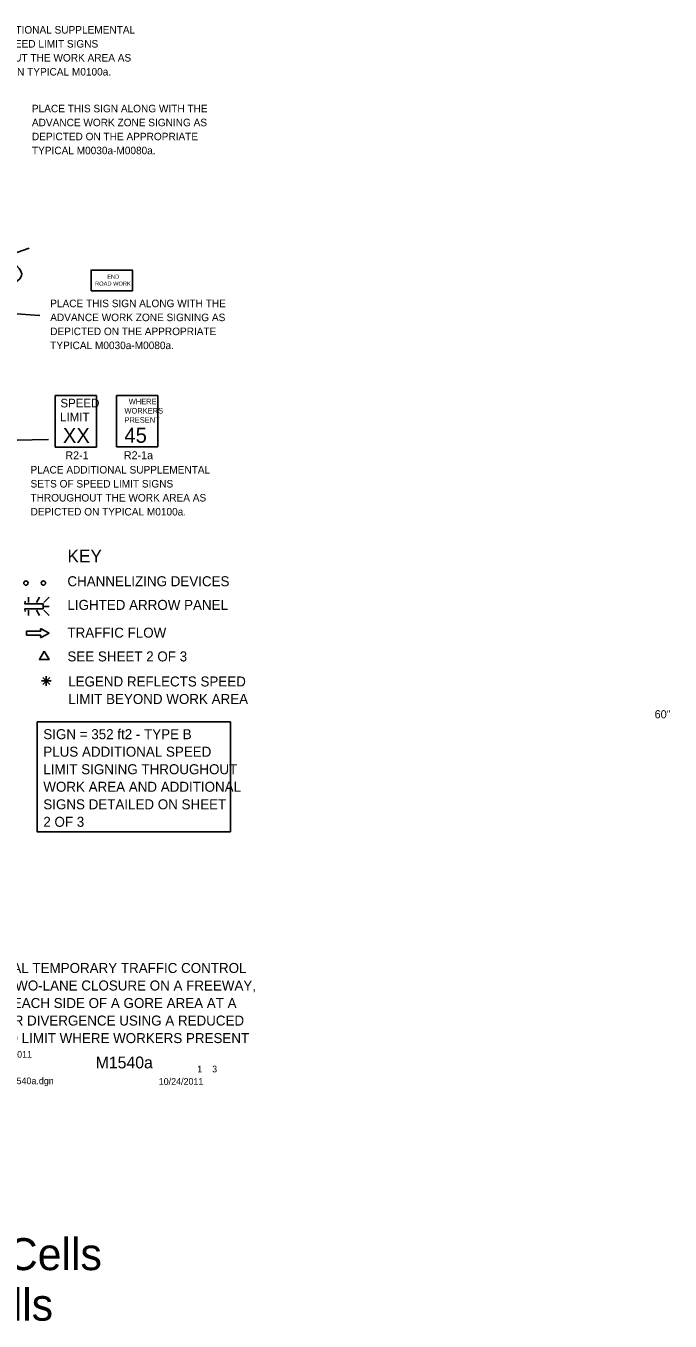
# Model space of a CAD drawing. Extents: x 16452 to 19504, y 5713 to 7079.
# Drawn here: x 17224 to 17823, y 5713 to 6918 of the extents above; entities that cross this region are included whole.
import ezdxf

# ---------------------------------------------------------------- set-up
doc = ezdxf.new("R2010")
doc.units = 0
for name, color, linetype in [('BORDER', 7, 'Continuous'), ('BORDER_SIGNAL_WO', 7, 'Continuous'), ('MT_SCRATCH_LEVEL_E', 7, 'Continuous'), ('PAVT_EDGE_EX', 7, 'Continuous'), ('TRAFFIC_SIGNS_PR', 7, 'Continuous'), ('TYPICAL_TEXT_DIMEN_EX', 7, 'Continuous'), ('TYPICAL_TEXT_DIMEN_PR', 7, 'Continuous')]:
    doc.layers.add(name, color=color, linetype=linetype)

msp = doc.modelspace()

# ---------------------------------------------------------------- linework, layer by layer
at = {"layer": 'MT_SCRATCH_LEVEL_E'}
for p, q in [((17238.3, 6354.9), (17225.1, 6354.9)), ((17225.1, 6354.9), (17225.1, 6351.2)), ((17225.1, 6351.2), (17238.3, 6351.2)), ((17238, 6356.7), (17238.3, 6354.9)), ((17238.3, 6351.2), (17238, 6349.4)), ((17245.9, 6353.1), (17238.7, 6357.2)), ((17238.7, 6348.9), (17245.9, 6353.1))]:
    msp.add_line(p, q, dxfattribs=at)
for centre, start, end in [((17238.5, 6356.8), 60.4248, 189.9638), ((17238.5, 6349.4), 170.0362, 299.7731)]:
    msp.add_arc(centre, 0.463, start, end, dxfattribs=at)
at = {"layer": 'PAVT_EDGE_EX'}
msp.add_arc((17319.9, 6425.6), 300, 107.923, 180, dxfattribs=at)
at = {"layer": 'TRAFFIC_SIGNS_PR'}
for p, q in [((17251.5, 6574.1), (17289.9, 6574.1)), ((17251.5, 6526.1), (17251.5, 6574.1)), ((17289.9, 6526.1), (17289.9, 6574.1)), ((17308.7, 6574.2), (17347.1, 6574.2)), ((17308.7, 6526.2), (17308.7, 6574.2)), ((17347.1, 6526.2), (17347.1, 6574.2)), ((17251.5, 6526.1), (17289.9, 6526.1)), ((17308.7, 6526.2), (17347.1, 6526.2)), ((17226.9, 6381.5), (17226.9, 6386.5)), ((17234.1, 6381.5), (17236.9, 6386.5)), ((17241, 6381.5), (17245.9, 6386.5)), ((17226.9, 6374.4), (17226.9, 6369.5)), ((17237, 6369.5), (17234.1, 6374.4)), ((17241, 6378), (17245.9, 6378)), ((17241, 6374.4), (17245.9, 6369.5))]:
    msp.add_line(p, q, dxfattribs=at)
msp.add_lwpolyline([(17285, 6671.5), (17323.4, 6671.5), (17323.4, 6690.7), (17285, 6690.7)], close=True, dxfattribs=at)
msp.add_lwpolyline([(17223.7, 6373.3), (17223.3, 6375.6), (17240.3, 6375.6), (17240.3, 6380.4), (17223.3, 6380.4), (17223.7, 6382.7)], dxfattribs=at)
for centre in [(17224.4, 6399.7), (17240.7, 6399.7)]:
    msp.add_circle(centre, 2, dxfattribs=at)
at = {"layer": 'TYPICAL_TEXT_DIMEN_EX'}
msp.add_lwpolyline([(17234.8, 6270.5), (17414.5, 6270.5), (17414.5, 6168.4), (17234.8, 6168.4)], close=True, dxfattribs=at)
at = {"layer": 'TYPICAL_TEXT_DIMEN_PR'}
for p, q in [((17240.1, 6311.7), (17246.5, 6305.4)), ((17246.5, 6311.7), (17240.1, 6305.4)), ((17243.3, 6308.6), (17243.3, 6313)), ((17243.3, 6308.6), (17238.8, 6308.6)), ((17243.3, 6308.6), (17246.5, 6308.6)), ((17243.3, 6308.6), (17247.8, 6308.6)), ((17243.3, 6308.6), (17243.3, 6304.1))]:
    msp.add_line(p, q, dxfattribs=at)
msp.add_lwpolyline([(17241.4, 6336.3), (17236.9, 6328.5), (17246, 6328.5)], close=True, dxfattribs=at)
for points in [[(17211.5, 6698.9), (17216.4, 6694.3), (17226.4, 6684.9), (17205.5, 6674.4), (17175.7, 6652.8), (17212.4, 6650.2), (17237.4, 6648.4)], [(17102.5, 6551), (17180.2, 6550.2), (17180.7, 6541.4), (17158.2, 6539.5), (17158, 6531.4), (17245.5, 6533)]]:
    msp.add_open_spline(points, degree=3, dxfattribs=at)

# ---------------------------------------------------------------- texts
at = {"layer": 'BORDER'}
for s, p in [('TYPICAL TEMPORARY TRAFFIC CONTROL', (17175.2, 6037.1)), ('FOR A TWO-LANE CLOSURE ON A FREEWAY,', (17165.4, 6020.8)), ('ONE ON EACH SIDE OF A GORE AREA AT A ', (17159.7, 6004.5)), ('MAJOR DIVERGENCE USING A REDUCED', (17178.5, 5988.2)), ('SPEED LIMIT WHERE WORKERS PRESENT', (17174.9, 5971.9))]:
    msp.add_text(s, height=9.3, dxfattribs=at).set_placement(p)
at = {"layer": 'BORDER_SIGNAL_WO'}
for s, height, p in [('    OCTOBER 2011    ', 6.2, (17159.1, 5958.3)), ('    M1540a   ', 11, (17272.9, 5948.4)), (' 1    3 ', 6.2, (17381.4, 5944.7)), ('PW RD/TS/Typicals/Signs/MT FWY/M1540a.dgn      ', 6.2, (17070.6, 5933.7)), ('10/24/2011    ', 6.2, (17347.9, 5933.1)), ('AS = 0.8 for Sign Cells', 29.727, (16894, 5760.8)), ('     1.0 for Text Cells', 29.727, (16894, 5713.8))]:
    msp.add_text(s, height=height, dxfattribs=at).set_placement(p)
at = {"layer": 'TRAFFIC_SIGNS_PR'}
for s, height, p in [('PLACE ADDITIONAL SUPPLEMENTAL', 7, (17159, 6910.6)), ('SETS OF SPEED LIMIT SIGNS', 7, (17159, 6897.6)), ('THROUGHOUT THE WORK AREA AS', 7, (17159, 6884.6)), ('DEPICTED ON TYPICAL M0100a.', 7, (17159, 6871.6)), ('PLACE THIS SIGN ALONG WITH THE', 7, (17230, 6837.4)), ('ADVANCE WORK ZONE SIGNING AS', 7, (17230, 6824.4)), ('DEPICTED ON THE APPROPRIATE', 7, (17230, 6811.4)), ('TYPICAL M0030a-M0080a.', 7, (17230, 6798.4)), ('END', 3.83, (17300, 6682.6)), ('ROAD WORK', 3.83, (17288.7, 6676.2)), ('PLACE THIS SIGN ALONG WITH THE', 7, (17247, 6656.2)), ('ADVANCE WORK ZONE SIGNING AS', 7, (17247, 6643.2)), ('DEPICTED ON THE APPROPRIATE', 7, (17247, 6630.2)), ('TYPICAL M0030a-M0080a.', 7, (17247, 6617.2)), ('SPEED', 8, (17256.5, 6563)), ('WHERE', 5.2, (17320, 6565.9)), ('LIMIT', 8, (17256.2, 6550.2)), ('WORKERS', 5.2, (17316, 6557.3)), ('PRESENT', 5.2, (17316, 6548.7)), ('XX', 14.03, (17258.8, 6529.9)), ('45', 14.03, (17316, 6530.1)), ('R2-1', 7.44, (17261.1, 6514.7)), ('R2-1a', 7.44, (17315.5, 6514.8)), ('PLACE ADDITIONAL SUPPLEMENTAL', 7, (17228.7, 6501.5)), ('SETS OF SPEED LIMIT SIGNS', 7, (17228.7, 6488.5)), ('THROUGHOUT THE WORK AREA AS', 7, (17228.7, 6475.5)), ('DEPICTED ON TYPICAL M0100a.', 7, (17228.7, 6462.5))]:
    msp.add_text(s, height=height, dxfattribs=at).set_placement(p)
at = {"layer": 'TYPICAL_TEXT_DIMEN_EX'}
for s, height, p in [('KEY', 12, (17263, 6418.8)), ('CHANNELIZING DEVICES', 9.3, (17263, 6396.7)), ('LIGHTED ARROW PANEL', 9.3, (17263, 6374.7)), ('TRAFFIC FLOW', 9.3, (17263, 6348.9)), ('SEE SHEET 2 OF 3', 9.3, (17263, 6326.8)), ('LEGEND REFLECTS SPEED', 9.3, (17263.7, 6303.5)), ('LIMIT BEYOND WORK AREA', 9.3, (17263.7, 6287.2)), ('SIGN = 352 ft2 - TYPE B', 9.3, (17240.6, 6254.5)), ('PLUS ADDITIONAL SPEED', 9.3, (17240.6, 6238.2)), ('LIMIT SIGNING THROUGHOUT', 9.3, (17240.6, 6221.9)), ('WORK AREA AND ADDITIONAL', 9.3, (17240.6, 6205.6)), ('SIGNS DETAILED ON SHEET', 9.3, (17240.6, 6189.3)), ('2 OF 3', 9.3, (17240.6, 6173))]:
    msp.add_text(s, height=height, dxfattribs=at).set_placement(p)
at = {"layer": 'TYPICAL_TEXT_DIMEN_PR'}
msp.add_text('60"', height=7.55, dxfattribs=at).set_placement((17808.9, 6273.9))

doc.saveas('drawing.dxf')
